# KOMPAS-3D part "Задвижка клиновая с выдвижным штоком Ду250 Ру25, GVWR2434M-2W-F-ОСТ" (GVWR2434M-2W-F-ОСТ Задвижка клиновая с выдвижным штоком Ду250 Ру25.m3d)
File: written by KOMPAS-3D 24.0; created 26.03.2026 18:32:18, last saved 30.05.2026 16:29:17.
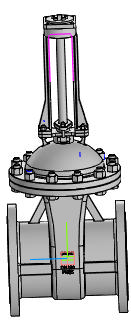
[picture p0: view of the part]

Document properties: Автор: R2D2; Полное имя файла: E:\Работа\Зайцев\GVWR2434M-2W-F-ОСТ Задвижка клиновая с выдвижным штоком DN.ru Ду50-300 Ру25\исходные материалы\DN250\GVWR2434M-2W-F-ОСТ Задвижка клиновая с выдвижным штоком Ду250 Ру25.m3d

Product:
- Component [detail]: AS 1110 - M10 x 35  | qty 4  | pos. 2  | Комментарий: Болты и винты   шестигранные точные   метрические ISO; Автор: R2D2; additional columns: Сталь, мягкая; source file: AS 1110 - M10 x 35 AS 1110 - M10 x 35.m3d
- Component [detail]: ANSI B18.2.4.2M - M10x1,5 - 16  | designation ANSI B18.2.4.2M - M10x1,5  | qty 4  | pos. 3  | Комментарий: Типы метрических   шестигранных гаек   2; Автор: R2D2; additional columns: Сталь, мягкая; source file: ANSI B18.2.4.2M - M10x1,5 ANSI B18.2.4.2M - M10x1,5 - 16.m3d
- Component [detail]: ANSI B18.2.4.2M - M8x1,25 - 13  | designation ANSI B18.2.4.2M - M8x1,25  | qty 1  | pos. 4  | Комментарий: Типы метрических   шестигранных гаек   2; Автор: R2D2; additional columns: Сталь, мягкая; source file: ANSI B18.2.4.2M - M8x1,25 ANSI B18.2.4.2M - M8x1,25 - 13.m3d
- Component [detail]: ANSI B18.2.4.2M - M20x2,5 - 30  | designation ANSI B18.2.4.2M - M20x2,5  | qty 12  | pos. 5  | Комментарий: Типы метрических   шестигранных гаек   2; Автор: R2D2; additional columns: Сталь, мягкая; source file: ANSI B18.2.4.2M - M20x2,5 ANSI B18.2.4.2M - M20x2,5 - 30.m3d
- Component [detail]: AS 1110 - M20 x 70  | qty 12  | pos. 6  | Комментарий: Болты и винты   шестигранные точные   метрические ISO; Автор: R2D2; additional columns: Сталь, мягкая; source file: AS 1110 - M20 x 70 AS 1110 - M20 x 70.m3d
- Component [detail]: Деталь1  | qty 1  | pos. 7  | Автор: R2D2; additional columns: Типовые; source file: 2.m3d
- Component [detail]: ANSI B18.2.4.2M - M8x1,25 - 13  | designation ANSI B18.2.4.2M - M8x1,25-01  | qty 1  | pos. 8  | Комментарий: Типы метрических   шестигранных гаек   2; Автор: R2D2; additional columns: Сталь, мягкая; source file: ANSI B18.2.4.2M - M8x1,25 ANSI B18.2.4.2M - M8x1,25 - 13.m3d
- Component [detail]: Фланец  | qty 2  | pos. 7  | Автор: R2D2; additional columns: Типовые; source file: Фланец DN250 Pn25 b36.m3d
- Component [detail]: Деталь1  | qty 1  | pos. 9  | Автор: R2D2; additional columns: Типовые; source file: Фланец Б.m3d
- Body: Тело 1  | qty 1
    Масса: 334.78834
- Body: Тело 2  | qty 1
    Масса: 334.78834
- Part/product: Задвижка клиновая с выдвижным штоком Ду250 Ру25  | designation GVWR2434M-2W-F-ОСТ
    Масса: 175
    Раздел спецификации: Прочие изделия
    Примечание: D040-07591

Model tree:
1. Массив по концентрической сетке:1  (labels: Грань.Твердое тело1)  (12 pattern instances)
     Шаг 2 = 360
2. Массив по сетке:1  (labels: Грань.Твердое тело1)  (4 pattern instances)
     Шаг 1 = 50; Угол раствора = 90; Шаг 2 = 120
3. Масштабирование:1
4. Масштабирование : Твердое тело1
5. Масштабирование : Solid1
6. Масштабирование : Ребро.Solid1  (with: Масштабирование : Solid1)  (labels: Твердое тело1; Solid1; Ребро.Solid1)
     Масштаб по оси Х = 1; Масштаб по оси Y = 1; Масштаб по оси Z = 1; Коэффициент = 1.25
7. Элемент выдавливания:1  (with: Грань.Элемент выдавливания:2, Грань.Элемент вращения:1)
     Расстояние 1 = 23.4956
8. Элемент выдавливания:2  (with: Грань.Элемент выдавливания:1, Грань.Элемент вращения:1)
     Расстояние 1 = 32.0521
9. Скругление:1  (with: Ребро.Элемент выдавливания:2, Ребро.Элемент выдавливания:1)
     Радиус = 10
10. Элемент выдавливания:3  (with: Грань.Элемент выдавливания:1)
     Расстояние 1 = 70
11. Эскиз:1  (with: Вершина.Элемент выдавливания:3)
12. Элемент выдавливания:4  (with: Грань.Элемент выдавливания:1)  (labels: Грань.Твердое тело1)
     Расстояние 1 = 253.633
13. Эскиз:2
14. Элемент выдавливания:5  (with: Грань.Элемент выдавливания:1)
     Расстояние 1 = 157.25; Смещение 1 = 1
15. Элемент по траектории:2  (with: Грань.Элемент выдавливания:3, Грань.Элемент вращения:1)  (labels: Грань.Твердое тело1; Грань.Solid1; Solid1; Твердое тело1)
     Длина траектории = 450.714; Ориентация = 2; Расстояние = -225; Ориентация = 2; Расстояние = -950

Referenced files in E:\Работа\Зайцев\GVWR2434M-2W-F-ОСТ Задвижка клиновая с выдвижным штоком DN.ru Ду50-300 Ру25\исходные материалы\DN250\: AS 1110 - M10 x 35 AS 1110 - M10 x 35.m3d, ANSI B18.2.4.2M - M10x1,5 ANSI B18.2.4.2M - M10x1,5 - 16.m3d, ANSI B18.2.4.2M - M8x1,25 ANSI B18.2.4.2M - M8x1,25 - 13.m3d, ANSI B18.2.4.2M - M20x2,5 ANSI B18.2.4.2M - M20x2,5 - 30.m3d, AS 1110 - M20 x 70 AS 1110 - M20 x 70.m3d, 2.m3d, Фланец DN250 Pn25 b36.m3d, Фланец Б.m3d
Referenced files in E:\Работа\Зайцев\GVWR3131M-2W-F-S Задвижка клиновая с выдвижным штоком DN.ru Ду50-200 Ру63\DN200\исходные материалы\: ANSI B18.2.4.2M - M20x2,5 ANSI B18.2.4.2M - M20x2,5 - 30.m3d, AS 1110 - M20 x 70 AS 1110 - M20 x 70.m3d, ANSI B18.2.4.2M - M10x1,5 ANSI B18.2.4.2M - M10x1,5 - 16.m3d, AS 1110 - M10 x 35 AS 1110 - M10 x 35.m3d
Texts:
  GVWR2434M-2W-F-ОСТ
  DN250
  GOST 26.020 Pr3
  PN25
  AS 1110 - M10 x 35 AS 1110 - M10 x 35 (1)
  ANSI B18.2.4.2M - M10x1,5 ANSI B18.2.4.2M - M10x1,5 - 16 (1)
  ANSI B18.2.4.2M - M8x1,25 ANSI B18.2.4.2M - M8x1,25 - 13
  ANSI B18.2.4.2M - M20x2,5 ANSI B18.2.4.2M - M20x2,5 - 30 (1)
  AS 1110 - M20 x 70 AS 1110 - M20 x 70 (1)
  Деталь1 Деталь1
  ANSI B18.2.4.2M - M20x2,5 ANSI B18.2.4.2M - M20x2,5 - 30 (2)
  AS 1110 - M20 x 70 AS 1110 - M20 x 70 (2)
  ANSI B18.2.4.2M - M20x2,5 ANSI B18.2.4.2M - M20x2,5 - 30 (3)
  AS 1110 - M20 x 70 AS 1110 - M20 x 70 (3)
  ANSI B18.2.4.2M - M20x2,5 ANSI B18.2.4.2M - M20x2,5 - 30 (4)
  AS 1110 - M20 x 70 AS 1110 - M20 x 70 (4)
  ANSI B18.2.4.2M - M20x2,5 ANSI B18.2.4.2M - M20x2,5 - 30 (5)
  AS 1110 - M20 x 70 AS 1110 - M20 x 70 (5)
  ANSI B18.2.4.2M - M20x2,5 ANSI B18.2.4.2M - M20x2,5 - 30 (6)
  AS 1110 - M20 x 70 AS 1110 - M20 x 70 (6)
  ANSI B18.2.4.2M - M20x2,5 ANSI B18.2.4.2M - M20x2,5 - 30 (7)
  AS 1110 - M20 x 70 AS 1110 - M20 x 70 (7)
  ANSI B18.2.4.2M - M20x2,5 ANSI B18.2.4.2M - M20x2,5 - 30 (8)
  AS 1110 - M20 x 70 AS 1110 - M20 x 70 (8)
  ANSI B18.2.4.2M - M20x2,5 ANSI B18.2.4.2M - M20x2,5 - 30 (9)
  AS 1110 - M20 x 70 AS 1110 - M20 x 70 (9)
  ANSI B18.2.4.2M - M20x2,5 ANSI B18.2.4.2M - M20x2,5 - 30 (10)
  AS 1110 - M20 x 70 AS 1110 - M20 x 70 (10)
  ANSI B18.2.4.2M - M20x2,5 ANSI B18.2.4.2M - M20x2,5 - 30 (11)
  AS 1110 - M20 x 70 AS 1110 - M20 x 70 (11)
  ANSI B18.2.4.2M - M20x2,5 ANSI B18.2.4.2M - M20x2,5 - 30 (12)
  AS 1110 - M20 x 70 AS 1110 - M20 x 70 (12)
  ANSI B18.2.4.2M - M10x1,5 ANSI B18.2.4.2M - M10x1,5 - 16 (2)
  AS 1110 - M10 x 35 AS 1110 - M10 x 35 (2)
  ANSI B18.2.4.2M - M10x1,5 ANSI B18.2.4.2M - M10x1,5 - 16 (3)
  AS 1110 - M10 x 35 AS 1110 - M10 x 35 (3)
  ANSI B18.2.4.2M - M10x1,5 ANSI B18.2.4.2M - M10x1,5 - 16 (4)
  AS 1110 - M10 x 35 AS 1110 - M10 x 35 (4)
  ANSI B18.2.4.2M - M8x1,25-01 ANSI B18.2.4.2M - M8x1,25 - 13
  Фланец (1)
  Фланец (2)
  Ось Y.Начало координат
  Ось Z.Начало координат
  Плоскость ZY.Начало координат
  Плоскость ZX.Начало координат
  Плоскость XY.Начало координат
